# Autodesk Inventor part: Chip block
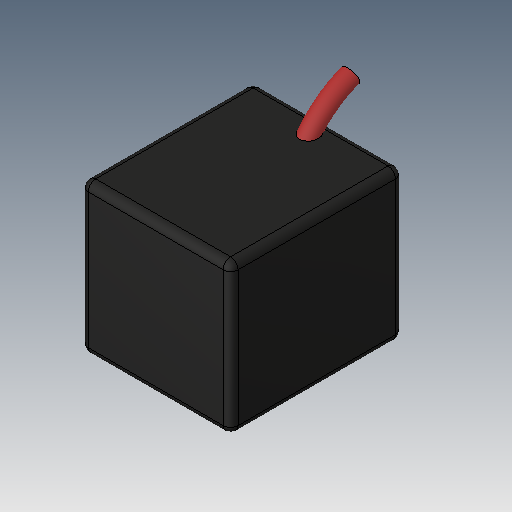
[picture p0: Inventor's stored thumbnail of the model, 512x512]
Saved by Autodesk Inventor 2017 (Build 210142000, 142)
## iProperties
Created: 2005-12
Part Number: Chip block
Material: Generic
Document SubType Name: Modeling
Designer: DanielSeverino
Density: 1 g/cm^3
Appearance: Default
Author: DanielSeverino
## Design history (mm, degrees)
feature "Solid1"
body "Solid2"
